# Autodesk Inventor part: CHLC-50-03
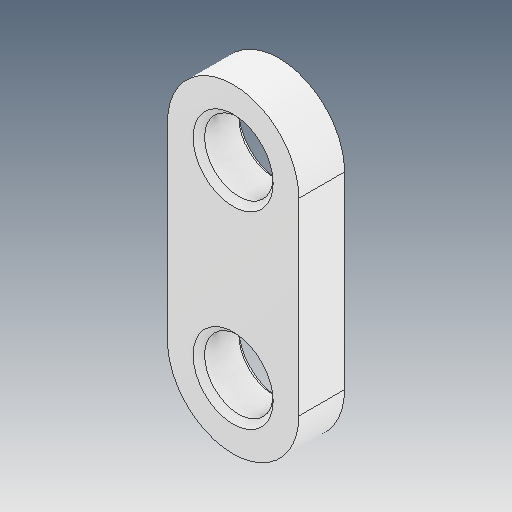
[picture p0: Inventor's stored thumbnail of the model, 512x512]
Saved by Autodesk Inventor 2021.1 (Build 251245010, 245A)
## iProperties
Created: 2021-05
Part Number: CHLC-50-03
Material: Ogólny
Document SubType Name: Modeling
Designer: user
Density: 1 g/cm^3
Appearance: Domyślna
Author: user
Revision Number: ÈÎºÎ
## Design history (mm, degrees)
feature "ÊäÈë1"
node "Bryła1"
